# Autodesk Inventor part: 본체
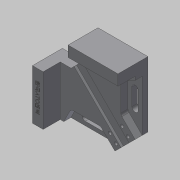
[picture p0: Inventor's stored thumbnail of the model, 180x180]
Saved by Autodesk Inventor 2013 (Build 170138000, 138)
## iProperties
Created: 2019-04
Part Number: 본체
Material: 일반
Document SubType Name: Modeling
Designer: Administrator
Density: 1 g/cm^3
Author: Administrator
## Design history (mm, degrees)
sketch "스케치1"
  geometry: L1 (-60, 60)-(60, 60); L2 (60, 60)-(60, -60); L3 (60, -60)-(-60, -60); L4 (-60, -60)-(-60, 60); L5 (-60, 60)-(60, -60); L6 (60, 60)-(-60, -60); 1 further point
  constraints: 12 end point, 2 midpoint, 2 parallel, 1 horizontal, 1 perpendicular
  dimensions: "d0" = 120 distance of L1.start L1.end; "d2" = 120 distance of L1.end L2.end
extrude "돌출1" new body sketch "스케치1" distance "d3" = 18; taper "d4" = 0 deg
sketch "스케치2"
  geometry: L1 (60, 60)-(-60, 60) reference; L2 (60, -60)-(60, 60) reference; L3 (-60, -60)-(-45, -60); L4 (-45, -60)-(-45, 10); L5 (-45, 10)-(-60, 10); L6 (-60, 10)-(-60, -60); L7 (-10, 45)-(60, 45); L8 (60, 45)-(60, 60); L9 (60, 60)-(-10, 60); L10 (-10, 60)-(-10, 45); 1 further point
  constraints: 16 end point, 4 parallel, 2 collinear, 2 horizontal, 2 perpendicular
  dimensions: "d5" = 50 distance between parallel lines of L5 L1; "d6" = 15 distance of L4.end L5.end; "d7" = 50 distance from line of L10 L1.end; "d8" = 15 distance of L7.end L8.end
extrude "돌출2" join sketch "스케치2" distance "d9" = 24; taper "d10" = 0 deg
sketch "스케치3"
  geometry: L1 (-45, -60)-(60, -60) reference; L2 (60, -60)-(60, 45) reference; L3 (-60, 10)-(-60, -60) reference; L4 (-40, -60)-(-30, -40); L5 (-30, -40)-(11.716, -40); L6 (11.716, -40)-(31.716, -60); L7 (-60, 10)-(-45, 10) reference; L8 (60, 40)-(40, 30); L9 (40, 30)-(40, -11.716); L10 (40, -11.716)-(60, -31.716); L11 (60, 60)-(-10, 60) reference; L12 (0, 0)-(60, -60); L13 (-45, 10)-(-45, -60) reference; L14 (-45, -60)-(60, -60) reference; L15 (60, -60)-(60, 45) reference; L16 (60, 45)-(-10, 45) reference; L17 (-10, 45)-(-10, 60) reference; L18 (-10, 60)-(-60, 60) reference; L19 (-60, 60)-(-60, 10) reference; L20 (-60, 10)-(-45, 10) reference
  constraints: 14 end point, 4 point on line, 2 parallel, 2 perpendicular, 1 other
  dimensions: "d13" = 20 distance from line of L4.start L3; "d14" = 30 distance from line of L4.end L3; "d24" = 20 distance from line of L8.start L11; "d28" = 30 vertical distance of L11.start L8.end; "d62" = 20 distance between parallel lines of L1 L5; "d63" = 20 distance between parallel lines of L2 L9; "d66" = 41.716 distance of L4.end L5.end
  node "투영된 루프1"
extrude "돌출3" cut sketch "스케치3" distance "d17" = 10; taper "d18" = 0 deg
sketch "스케치4"
  geometry: L1 (-60, 10)-(-60, -60) reference; L2 (-20, -45.5)-(4, -45.5); L3 (-20, -54.5)-(4, -54.5); L4 (-40, -60)-(-30, -40) reference; L5 (31.716, -60)-(-40, -60) reference; A1 r 4.5 centre (-20, -50) between (-20, -45.5) and (-20, -54.5); A2 r 4.5 centre (4, -50) between (4, -45.5) and (4, -54.5); 2 further points
  constraints: 4 end point, 4 point on circle, 4 tangent, 2 centre point, 2 horizontal alignment, 1 equal radius, 1 midpoint
  dimensions: "d19" = 40 distance from line of A1.centre L1; "d20" = 24 distance of A2.centre A1.centre; "d21" = 9 distance between parallel lines of L3 L2
extrude "돌출4" cut sketch "스케치4" stored distance "d22" = 10; taper "d23" = 0 deg
extrude "돌출5" cut sketch "스케치3" distance "d29" = 10; taper "d30" = 0 deg
sketch "스케치5"
  geometry: L1 (40, 30)-(60, 40) reference; L2 (60, -31.716)-(40, -11.716) reference; L3 (54.5, -4)-(54.5, 20); L4 (45.5, -4)-(45.5, 20); L5 (-60, 60)-(60, 60) reference; L6 (60, 60)-(60, -60) reference; A1 r 4.5 centre (50, -4) between (54.5, -4) and (45.5, -4); A2 r 4.5 centre (50, 20) between (54.5, 20) and (45.5, 20); 3 further points
  constraints: 4 end point, 4 point on circle, 4 tangent, 2 centre point, 2 midpoint, 2 vertical alignment, 1 equal radius
  dimensions: "d32" = 9 diameter of A2; "d34" = 24 distance of A2.centre A1.centre; "d35" = 40 vertical distance of A2.centre L5.end
extrude "돌출6" cut sketch "스케치5" stored distance "d36" = 10; taper "d37" = 0 deg
sketch "스케치6"
  geometry: L1 (-10, 45)-(-10, 60) reference; L2 (-10, 60)-(-60, 60) reference; L3 (-60, 60)-(-60, 10) reference; L4 (-60, 10)-(-45, 10) reference; L5 (31.716, -60)-(60, -60) reference; L6 (60, -60)-(60, -31.716) reference; L7 (40, -11.716)-(40, 30) reference; L8 (-45, 10)-(-29.806, 10); L9 (-10, 10)-(-10, 29.806); L10 (-60, 60)-(60, -60); L11 (31.716, -60)-(60, -31.716); L12 (-29.806, 10)-(-10, 29.806); L13 (-10, 29.806)-(-10, 45); L14 (-29.806, 10)-(-10, 10); L15 (-25.56, 14.246)-(48.686, -60); L16 (-14.246, 25.56)-(60, -48.686); 3 further points
  constraints: 18 end point, 8 perpendicular, 7 point on line, 1 coincident, 1 midpoint, 1 parallel, 1 other
  dimensions: "d45" = 20 distance from line of L5.end L11; "d46" = 93 distance between parallel lines of L12 L11; "d49" = 16 distance between parallel lines of L16 L15
extrude "돌출7" cut sketch "스케치6" stored distance "d47" = 10; taper "d48" = 0 deg
sketch "스케치8"
  geometry: L1 (-10, 45)-(-10, 29.806) reference; L2 (-10, 29.806)-(-29.806, 10) reference; L3 (-29.806, 10)-(-45, 10) reference; L4 (-45, 10)-(-45, -60) reference; L5 (-45, -60)-(-40, -60) reference; L6 (-40, -60)-(-30, -40) reference; L7 (-30, -40)-(11.716, -40) reference; L8 (11.716, -40)-(31.716, -60) reference; L9 (31.716, -60)-(60, -60) reference; L10 (60, -60)-(60, -31.716) reference; L11 (60, -31.716)-(40, -11.716) reference; L12 (40, -11.716)-(40, 30) reference; L13 (40, 30)-(60, 40) reference; L14 (60, 40)-(60, 45) reference; L15 (60, 45)-(-10, 45) reference; 1 further point
sketch "스케치9"
  geometry: L1 (31.716, -60)-(60, -60) reference; L2 (60, -60)-(60, -31.716) reference; L3 (31.716, -60)-(60, -31.716); 1 further point
  constraints: 2 end point, 2 point on line
  dimensions: "d52" = 20 distance from line of L1.end L3; "d53" = 40 distance of L3.start L3.end
extrude "돌출9" cut sketch "스케치9" stored distance "d54" = 3.5; taper "d55" = 0 deg
sketch "스케치10"
  geometry: L1 (29.806, 10)-(10, 29.806) reference; L2 (19.903, 19.903)-(-45.858, -45.858); L3 (15.66, 24.146)-(-50.101, -41.615); L4 (24.146, 15.66)-(-41.615, -50.101); L5 (-41.615, -50.101)-(-50.101, -41.615); L6 (24.146, 15.66)-(15.66, 24.146); 3 further points; 1 other entity
  constraints: 10 end point, 2 point on line, 1 collinear, 1 midpoint, 1 perpendicular, 8 other
  dimensions: "d56" = 12 distance between parallel lines of L4 L3
extrude "돌출10" cut sketch "스케치10" distance "d58" = 3; taper "d59" = 0 deg
extrude "돌출11" cut sketch "스케치6" distance "d60" = 3.5; taper "d61" = 0 deg
sketch "스케치12"
  geometry: L1 (-50.101, -41.615)-(15.66, 24.146) reference; L2 (-60, -31.716)-(-50.101, -41.615) reference; 3 further points
  dimensions: "d67" = 6 distance from line of L1 point (-50.101, -33.13); "d68" = 6 distance from line of L1 point (-41.615, -24.645); "d69" = 6 distance from line of L2 point (-50.101, -33.13); "d70" = 12 distance of point (-41.615, -24.645) point (-50.101, -33.13)
hole "구멍1" sketch "스케치12" at (-50.101, -33.13), (-41.615, -24.645) diameter "d71" = 4.5; stored, may be unused: countersink angle "d75" = 90 deg, drill point angle "d77" = 118 deg; dims "d72" = 6, "d73" = 8, "d74" = 10, "d76" = 8
sketch "스케치13"
  geometry: L1 (24.146, 15.66)-(-41.615, -50.101) reference; L2 (-41.615, -50.101)-(-31.716, -60) reference; 3 further points
  dimensions: "d78" = 6 distance from line of point (-33.13, -50.101) L1; "d79" = 6 distance from line of point (-24.645, -41.615) L1; "d80" = 6 distance from line of point (-33.13, -50.101) L2; "d81" = 12 distance of point (-24.645, -41.615) point (-33.13, -50.101)
hole "구멍2" sketch "스케치13" at (-33.13, -50.101), (-24.645, -41.615) diameter "d82" = 4.5; stored, may be unused: countersink angle "d86" = 90 deg, drill point angle "d88" = 118 deg; dims "d83" = 6, "d84" = 8, "d85" = 10, "d87" = 8
sketch "스케치14"
  geometry: L1 (-45, -60)-(-45, 10) reference; L2 (-45, 10)-(-60, 10) reference; 2 further points
  constraints: 1 other
  dimensions: "d89" = 35 distance from line of point (-52.5, -25) L2; "d90" = 7.5 distance from line of L1 point (-52.5, -25)
feature "엠보싱1" sketch "스케치14" dims "d0" = 120, "d2" = 120, "d91" = 0.5, "d92" = 0
fillet "모깎기1" dims "d93" = 5
extrude "돌출8" cut sketch "스케치6" distance "d50" = 3.5; taper "d51" = 0 deg
node "솔리드1"
